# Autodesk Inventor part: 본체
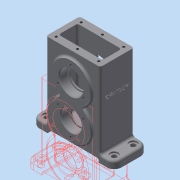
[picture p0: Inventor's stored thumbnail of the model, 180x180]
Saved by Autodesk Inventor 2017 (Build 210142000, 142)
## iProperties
Created: 2020-03
Part Number: 본체
Material: 알루미늄 6061
Document SubType Name: Modeling
Designer: mduedu
Density: 2.71 g/cm^3
Mass: 597.031 g
Surface Area: 576.062 cm^2
Volume: 220.307 cm^3
Appearance: 기본값
Author: mduedu
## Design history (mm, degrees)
sketch "스케치1"
  geometry: L1 (-56, 0)-(56, 0); L2 (56, 0)-(56, 10); L3 (-56, 10)-(-56, 0); L4 (37, 10)-(37, 114); L5 (37, 114)-(-37, 114); L6 (-37, 114)-(-37, 10); L7 (56, 10)-(37, 10); L8 (-37, 10)-(-56, 10); L9 (0, 0)-(0, 114); 1 further point
  constraints: 18 end point, 5 parallel, 2 midpoint, 2 vertical, 1 coincident, 1 horizontal, 1 perpendicular
  dimensions: "d0" = 112 distance of L1.start L1.end; "d2" = 10 distance of L1.end L2.end; "d3" = 114 distance between parallel lines of L5 L1; "d4" = 74 distance between parallel lines of L4 L6
extrude "돌출1" new body sketch "스케치1" stored distance "d5" = 46; taper "d6" = 0 deg
sketch "스케치2"
  geometry: L1 (56, 0)-(-56, 0) reference; C1 r 26 at (0, 34); C2 r 26 at (0, 79); 1 further point
  constraints: 2 centre point, 2 vertical alignment, 1 equal radius
  dimensions: "d7" = 52 diameter of C2; "d9" = 34 distance from line of C1.centre L1; "d10" = 45 distance of C2.centre C1.centre
extrude "돌출2" join sketch "스케치2" stored distance "d11" = 52; taper "d12" = 0 deg
fillet "모깎기1" dims "d13" = 3
fillet "모깎기2" dims "d14" = 3
fillet "모깎기3" dims "d15" = 10
fillet "모깎기4" dims "d16" = 3
fillet "모깎기5" dims "d17" = 3
sketch "스케치3"
  geometry: L1 (-30, 114)-(30, 114); L2 (30, 114)-(30, 13); L3 (30, 13)-(-30, 13); L4 (-30, 13)-(-30, 114); L5 (-34, 114)-(34, 114) reference; L6 (46, 0)-(-46, 0) reference; 2 further points
  constraints: 8 end point, 2 parallel, 1 collinear, 1 horizontal, 1 midpoint, 1 perpendicular, 1 vertical alignment
  dimensions: "d18" = 60 distance between parallel lines of L2 L4; "d20" = 13 distance between parallel lines of L3 L6
extrude "돌출3" cut sketch "스케치3" stored distance "d21" = 26; taper "d22" = 0 deg
fillet "모깎기6" dims "d23" = 3
fillet "모깎기7" dims "d24" = 3
sketch "스케치4"
  geometry: L1 (-35, 0)-(35, 0); L2 (35, 0)-(35, 5); L3 (35, 5)-(-35, 5); L4 (-35, 5)-(-35, 0); 2 further points
  constraints: 8 end point, 2 parallel, 1 coincident, 1 horizontal, 1 midpoint, 1 perpendicular
  dimensions: "d25" = 70 distance of L1.start L1.end; "d27" = 5 distance of L1.end L2.end
extrude "돌출4" cut sketch "스케치4" stored distance "d28" = 26; taper "d29" = 0 deg
fillet "모깎기8" dims "d30" = 3
sketch "스케치5"
  geometry: A1 r 10 centre (-86, 33) between (-86, 43) and (-96, 33) reference; A2 r 10 centre (-86, 7) between (-96, 7) and (-86, -3) reference; A3 r 10 centre (6, 7) between (6, -3) and (16, 7) reference; A4 r 10 centre (6, 33) between (16, 33) and (6, 43) reference; 5 further points
  constraints: 4 coincident
hole "구멍1" sketch "스케치5" at (-86, 33), (-86, 7), (6, 7), (6, 33) diameter "d31" = 6.6; stored, may be unused: countersink angle "d35" = 90 deg, drill point angle "d37" = 118 deg; dims "d32" = 6, "d33" = 11, "d34" = 2, "d36" = 8
sketch "스케치6"
  geometry: A1 r 26 centre (0, 34) between (-16.403, 54.172) and (16.403, 54.172) reference; A2 r 3 centre (18.296, 56.5) between (16.403, 58.828) and (16.403, 54.172) reference; A3 r 26 centre (0, 79) between (16.403, 58.828) and (-16.403, 58.828) reference; A4 r 3 centre (-18.296, 56.5) between (-16.403, 54.172) and (-16.403, 58.828) reference; 2 further points
  constraints: 1 coincident
hole "구멍2" sketch "스케치6" at (0, 79) diameter "d38" = 28; stored, may be unused: countersink angle "d42" = 90 deg, drill point angle "d44" = 118 deg; dims "d39" = 6, "d40" = 32, "d41" = 11, "d43" = 8
sketch "스케치7"
  geometry: C1 r 16 at (0, 79) reference; A1 r 26 centre (0, 34) between (-16.403, 54.172) and (16.403, 54.172) reference; A2 r 3 centre (18.296, 56.5) between (16.403, 58.828) and (16.403, 54.172) reference; A3 r 26 centre (0, 79) between (16.403, 58.828) and (-16.403, 58.828) reference; A4 r 3 centre (-18.296, 56.5) between (-16.403, 54.172) and (-16.403, 58.828) reference; 2 further points
  constraints: 1 coincident
hole "구멍3" sketch "스케치7" at (0, 34) diameter "d45" = 24; stored, may be unused: countersink angle "d49" = 90 deg, drill point angle "d51" = 118 deg; dims "d46" = 6, "d47" = 28, "d48" = 11, "d50" = 8
sketch "스케치8"
  geometry: C1 r 14 at (0, 34) reference; A1 r 26 centre (0, 34) between (-16.403, 54.172) and (16.403, 54.172) reference; A2 r 3 centre (18.296, 56.5) between (16.403, 58.828) and (16.403, 54.172) reference; A3 r 26 centre (0, 79) between (16.403, 58.828) and (-16.403, 58.828) reference; A4 r 3 centre (-18.296, 56.5) between (-16.403, 54.172) and (-16.403, 58.828) reference; 2 further points
  constraints: 1 coincident
hole "구멍4" sketch "스케치8" at (0, 79) diameter "d52" = 24; stored, may be unused: countersink angle "d56" = 90 deg, drill point angle "d58" = 118 deg; dims "d53" = 6, "d54" = 28, "d55" = 11, "d57" = 8
sketch "스케치9" dims "d59" = 40
  geometry: C1 r 14 at (0, 34) reference; C2 r 16 at (0, 79) reference; A1 r 26 centre (0, 34) between (-16.403, 54.172) and (16.403, 54.172) reference; A2 r 3 centre (18.296, 56.5) between (16.403, 58.828) and (16.403, 54.172) reference; A3 r 26 centre (0, 79) between (16.403, 58.828) and (-16.403, 58.828) reference; A4 r 3 centre (-18.296, 56.5) between (-16.403, 54.172) and (-16.403, 58.828) reference; 3 further points
  constraints: 2 vertical alignment, 1 coincident, 2 other
hole "구멍5" sketch "스케치9" at (0, 99) diameter "d61" = 3.242; stored, may be unused: countersink angle "d65" = 90 deg, drill point angle "d67" = 118 deg; dims "d62" = 8, "d63" = 28, "d64" = 11, "d66" = 10
sketch "스케치10" dims "d71" = 40
  geometry: C1 r 1.621 at (17.321, 69) reference; C2 r 1.621 at (-17.321, 69) reference; C3 r 1.621 at (0, 99) reference; C4 r 14 at (0, 34) reference; C5 r 16 at (0, 79) reference; A1 r 26 centre (0, 34) between (-16.403, 54.172) and (16.403, 54.172) reference; A2 r 3 centre (18.296, 56.5) between (16.403, 58.828) and (16.403, 54.172) reference; A3 r 26 centre (0, 79) between (16.403, 58.828) and (-16.403, 58.828) reference; A4 r 3 centre (-18.296, 56.5) between (-16.403, 54.172) and (-16.403, 58.828) reference; 3 further points
  constraints: 2 vertical alignment, 1 coincident, 2 other
hole "구멍6" sketch "스케치10" at (0, 14) diameter "d72" = 3.242; stored, may be unused: countersink angle "d76" = 90 deg, drill point angle "d78" = 118 deg; dims "d73" = 8, "d74" = 28, "d75" = 11, "d77" = 10
sketch "스케치11"
  geometry: L1 (5, 6)-(63, 6); L2 (63, 6)-(63, 40); L3 (63, 40)-(5, 40); L4 (5, 40)-(5, 6); L5 (5, 6)-(63, 40); L6 (63, 6)-(5, 40); 7 further points
  constraints: 12 end point, 4 coincident, 4 midpoint, 2 parallel, 1 horizontal, 1 perpendicular
  dimensions: "d82" = 58 distance of L3.end L2.end; "d83" = 34 distance of L2.end L1.end
hole "구멍7" sketch "스케치11" at (5, 40), (63, 40), (63, 6), (5, 6), (34, 6), (34, 40) diameter "d84" = 3.242; stored, may be unused: countersink angle "d88" = 90 deg, drill point angle "d90" = 118 deg; dims "d85" = 8, "d86" = 28, "d87" = 11, "d89" = 10
fillet "모깎기9" dims "d91" = 0.3
chamfer "모따기1" distance "d92" = 1; stored, may be unused: second distance "d93" = 2, angle "d94" = 45 deg
sketch "스케치12"
  geometry: 2 further points
  constraints: 1 coincident
hole "구멍8" sketch "스케치12" at (0, -23) diameter "d95" = 4.917; stored, may be unused: countersink angle "d99" = 90 deg, drill point angle "d101" = 118 deg; dims "d96" = 8, "d97" = 12, "d98" = 1, "d100" = 10
sketch "스케치13"
  geometry: L1 (33, -13)-(7, -13) reference; L2 (40, 101)-(0, 101) reference; 3 further points
  constraints: 1 midpoint, 1 vertical alignment, 1 other
  dimensions: "d102" = 40 distance from line of point (20, 61) L2
feature "엠보싱1" sketch "스케치13" dims "d0" = 112, "d2" = 10, "d3" = 114, "d4" = 74, "d13" = 3, "d103" = 0.5, "d104" = 0
node "솔리드1"
mirror "대칭1"
pattern_circular "원형 패턴1" dims angle "d69" = 360 deg
pattern_circular "원형 패턴2" dims angle "d80" = 360 deg
mirror "대칭2"
node "투영된 루프1"
node "투영된 루프2"
node "투영된 루프3"
node "투영된 루프4"
node "투영된 루프5"
